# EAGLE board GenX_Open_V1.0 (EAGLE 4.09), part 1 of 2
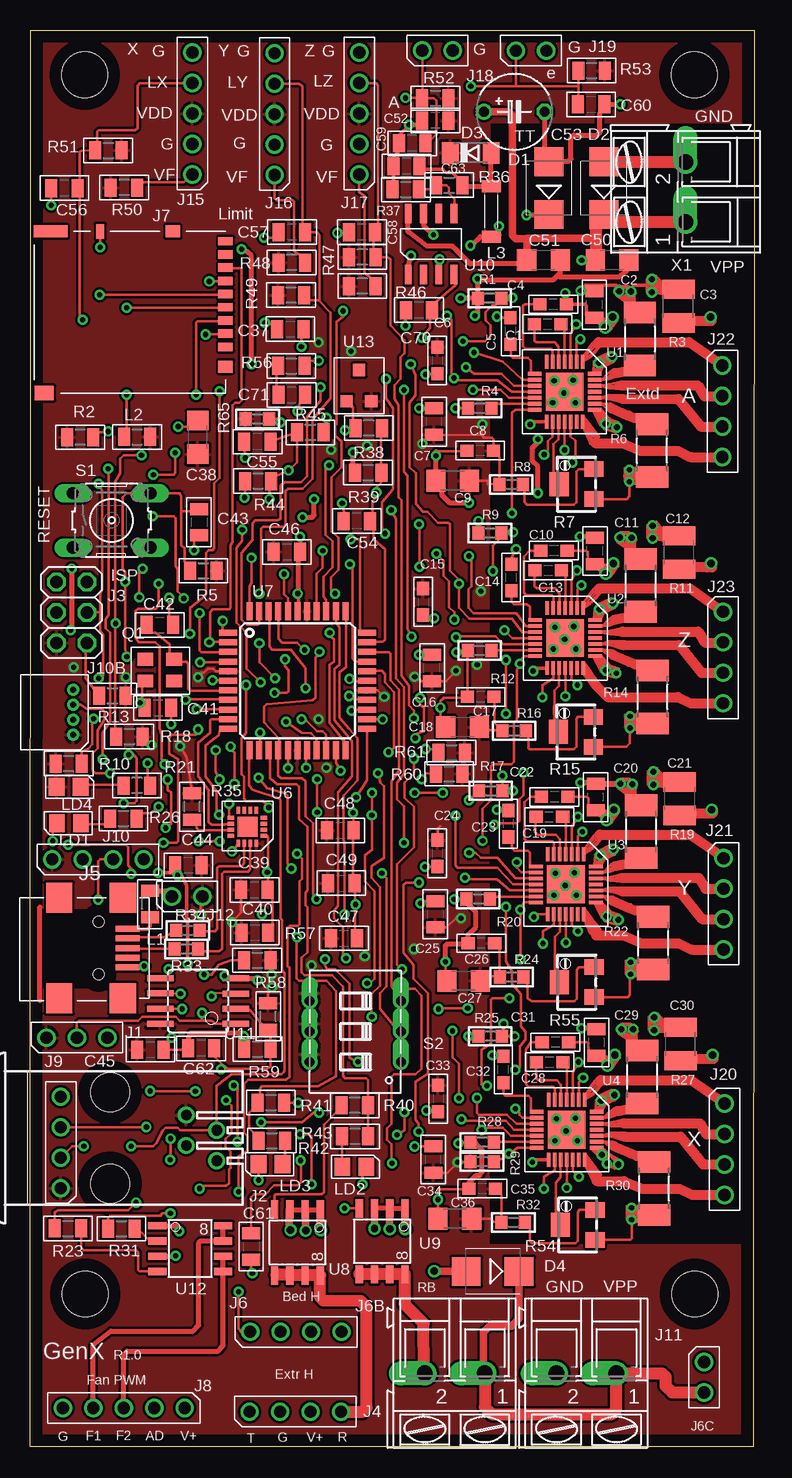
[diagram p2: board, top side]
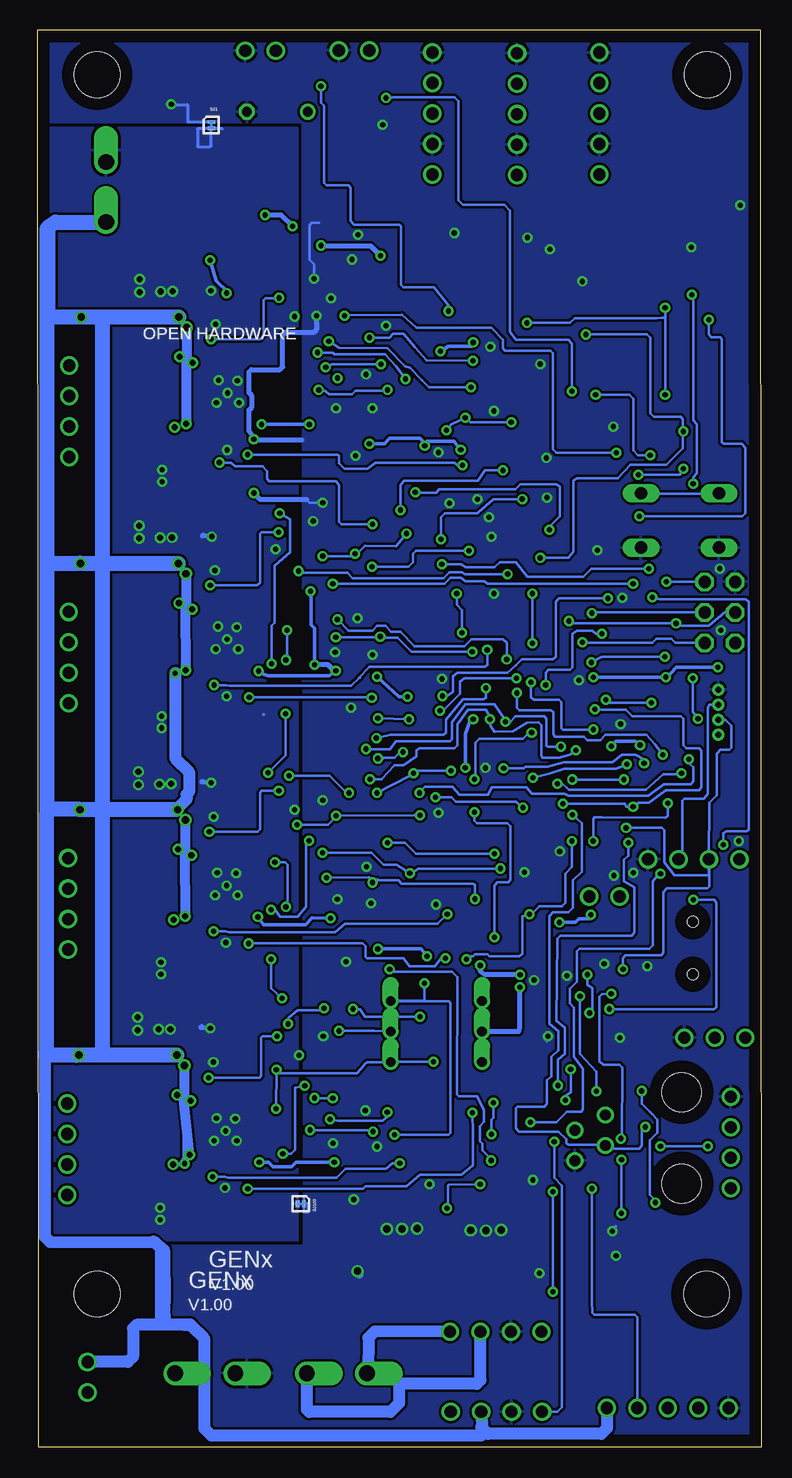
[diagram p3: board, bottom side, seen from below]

Size 60.4 x 118.06 mm. Coordinates in mm from the lower left corner, seen from the top.
Outline: 60.33,0 0,0 0.08,118.06 60.4,118.06 60.33,0
Copper layers used: Top, Bottom
Holes 3.81 mm at 4.6,12.73 55.42,12.73 4.55,114.33 55.4,114.33

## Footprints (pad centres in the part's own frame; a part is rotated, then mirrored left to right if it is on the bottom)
C0603 = smd 1.1 x 1: 1 -1.104,0; 2 1.104,0
C0805 = smd 1 x 1.5: 1 -1.1,0; 2 1.1,0
C1210 = smd 1.6 x 2.7: 1 -1.4,0; 2 1.4,0
C1206 = smd 1.6 x 1.8: 1 -1.4,0; 2 1.4,0
TAP5-60 = drill 0.813 round: + -2.54,0 | drill 0.813 octagon: - 2.54,0
SMB = smd 2.4 x 2.4: A 2.2,0; C -2.2,0
SOD80C = smd 1.4 x 1.8: A 1.7,0; C -1.7,0
520241-2 = drill 0.889 round: 1 -1.905,6.35; 2 -0.635,8.89; 3 0.635,6.35; 4 1.905,8.89 | hole 3.251: -3.81,0; 3.81,0
1X4ROUND = drill 1.016 round: 1 -3.81,0; 2 -1.27,0; 3 1.27,0; 4 3.81,0
2X03 = drill 1.016 octagon: 1 -2.54,-1.27; 2 -2.54,1.27; 3 0,-1.27; 4 0,1.27; 5 2.54,-1.27; 6 2.54,1.27
USB-BMINI = smd 0.5 x 2: 1 -1.6,2.4; 2 -0.8,2.4; 3 0,2.4; 4 0.8,2.4; 5 1.6,2.4 | smd 2.5 x 2.2: P$6 -4.2,2; P$7 4.2,2; P$8 4.2,-3.3; P$9 -4.2,-3.3 | hole 0.9: -2.182,0; 2.182,0
AK300/2 = drill 1.321 offset: 1 -2.515,0; 2 2.489,0
1X2ROUND = drill 1.016 round: 1 -1.27,0; 2 1.27,0
USD2 = smd 0.7 x 1.2: 1 3.85,0; 2 2.75,0; 3 1.65,0; 4 0.55,0; 5 -0.55,0; 6 -1.65,0; 7 -2.75,0; 8 -3.85,0; 9 -4.95,0 | smd 1.2 x 0.7: 10 -5.775,-10.45 | smd 1 x 2.8: P$1 -5.775,-14.575 | smd 1 x 1.2: P$9 5.5,0; P$10 -5.775,-4.4 | smd 1.2 x 1.6: P$11 7.7,-15.125
1X5ROUND = drill 1.016 round: 1 -5.08,0; 2 -2.54,0; 3 0,0; 4 2.54,0; 5 5.08,0
1X3ROUND = drill 1.016 round: 1 -2.54,0; 2 0,0; 3 2.54,0
1X4MOLEX = drill 0.5 pad 0.9 round: 1 1.875,0; 2 0.625,0; 3 -0.625,0; 4 -1.875,0
R0805 = smd 1 x 1.5: 1 -1.1,0; 2 1.1,0
L4516C = smd 1 x 1.6: 1 -2.1,0; 2 2.1,0
805SMT = smd 1.3 x 1.5: P$1 -1,0; P$2 1,0
ABM8 = smd 1.3 x 1.05: 1 -1.2,-0.9; 2 1.2,-0.9; 3 1.2,0.9; 4 -1.2,0.9
R0603 = smd 1 x 1.1: 1 -0.977,0; 2 0.977,0
R2010 = smd 1.8 x 2.7: 1 -2.2,0; 2 2.2,0
RTRIM5W = smd 1.3 x 1.6: 1 -1.25,-1.45; 3 1.25,-1.45 | smd 2 x 1.6: 2 0,1.45
B3F-10XX = drill 1.016 long: 1 -3.251,2.261; 2 3.251,2.261; 3 -3.251,-2.261; 4 3.251,-2.261
DIP03YL = drill 0.813 offset: 1 -2.54,-3.81; 2 0,-3.81; 3 2.54,-3.81; 4 2.54,3.81; 5 0,3.81; 6 -2.54,3.81
SJS = smd 0.305 x 0.61: 1 -0.267,0; 2 0.267,0
QFN28ET = smd 1.15 x 0.3: 1 -2.5,1.5; 2 -2.5,1; 3 -2.5,0.5; 4 -2.5,0; 5 -2.5,-0.5; 6 -2.5,-1; 7 -2.5,-1.5; 15 2.5,-1.5; 16 2.5,-1; 17 2.5,-0.5; 18 2.5,0; 19 2.5,0.5; 20 2.5,1; 21 2.5,1.5 | smd 0.3 x 1.15: 8 -1.5,-2.5; 9 -1,-2.5; 10 -0.5,-2.5; 11 0,-2.5; 12 0.5,-2.5; 13 1,-2.5; 14 1.5,-2.5; 22 1.5,2.5; 23 1,2.5; 24 0.5,2.5; 25 0,2.5; 26 -0.5,2.5; 27 -1,2.5; 28 -1.5,2.5 | smd 3.15 x 3.15: P$1 0,0
QFN16-3 = smd 0.55 x 0.3: 1 -1.375,0.75; 2 -1.375,0.25; 3 -1.375,-0.25; 4 -1.375,-0.75; 9 1.375,-0.75; 10 1.375,-0.25; 11 1.375,0.25; 12 1.375,0.75 | smd 0.3 x 0.55: 5 -0.75,-1.375; 6 -0.25,-1.375; 7 0.25,-1.375; 8 0.75,-1.375; 13 0.75,1.375; 14 0.25,1.375; 15 -0.25,1.375; 16 -0.75,1.375 | smd 1.65 x 1.65: P$1 0,0
TQFP44 = smd 1.5 x 0.5: 1 -5.8,4; 2 -5.8,3.2; 3 -5.8,2.4; 4 -5.8,1.6; 5 -5.8,0.8; 6 -5.8,0; 7 -5.8,-0.8; 8 -5.8,-1.6; 9 -5.8,-2.4; 10 -5.8,-3.2; 11 -5.8,-4; 23 5.8,-4; 24 5.8,-3.2; 25 5.8,-2.4; 26 5.8,-1.6; 27 5.8,-0.8; 28 5.8,0; 29 5.8,0.8; 30 5.8,1.6; 31 5.8,2.4; 32 5.8,3.2; 33 5.8,4 | smd 0.5 x 1.5: 12 -4,-5.8; 13 -3.2,-5.8; 14 -2.4,-5.8; 15 -1.6,-5.8; 16 -0.8,-5.8; 17 0,-5.8; 18 0.8,-5.8; 19 1.6,-5.8; 20 2.4,-5.8; 21 3.2,-5.8; 22 4,-5.8; 34 4,5.8; 35 3.2,5.8; 36 2.4,5.8; 37 1.6,5.8; 38 0.8,5.8; 39 0,5.8; 40 -0.8,5.8; 41 -1.6,5.8; 42 -2.4,5.8; 43 -3.2,5.8; 44 -4,5.8
SO-8 = smd 0.61 x 1.524: 1 -1.905,-2.743; 2 -0.635,-2.743; 3 0.635,-2.743; 4 1.905,-2.743; 5 1.905,2.743; 6 0.635,2.743; 7 -0.635,2.743; 8 -1.905,2.743
SO8 = smd 0.559 x 1.651: 1 -1.905,-2.54; 2 -0.635,-2.54; 3 0.635,-2.54; 4 1.905,-2.54; 5 1.905,2.54; 6 0.635,2.54; 7 -0.635,2.54; 8 -1.905,2.54
SOIC-8 = smd 0.5 x 2.2: 1 -1.905,-3.154; 2 -0.645,-3.154; 3 0.625,-3.154; 4 1.895,-3.154; 5 1.905,3.154; 6 0.635,3.154; 7 -0.635,3.154; 8 -1.905,3.154
SOT-23 = smd 1.03 x 1.03: 1 -1.038,-1.038; 2 1.038,-1.038; 3 0,1.556

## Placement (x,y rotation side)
C1  0.1uF  [C0603]  43.64,95.2 180 top
C2  0.1uF  [C0805]  47.07,95.17 90 top
C3  10uF  [C1210]  54.08,95.05 90 top
C4  0.1uF  [C0603]  43.15,93.55 0 top
C5  0.22uF  [C0603]  40.08,92.96 90 top
C6  0.1uF  [C0603]  33.96,90.53 270 top
C7  0.1uF  [C0805]  33.71,85.42 90 top
C8  0.1uF  [C0603]  37.54,83.01 180 top
C9  10uF  [C1206]  35.26,80.49 180 top
C10  0.1uF  [C0603]  43.69,74.68 180 top
C11  0.1uF  [C0805]  47.12,74.65 90 top
C12  10uF  [C1210]  54.13,74.52 90 top
C13  0.1uF  [C0603]  43.21,73.03 0 top
C14  0.22uF  [C0603]  40.13,72.44 90 top
C15  0.1uF  [C0603]  32.79,70.41 270 top
C16  0.1uF  [C0805]  33.53,64.9 90 top
C17  0.1uF  [C0603]  37.59,62.48 180 top
C18  10uF  [C1206]  36.07,59.97 180 top
C19  0.1uF  [C0603]  43.74,54.15 180 top
C20  0.1uF  [C0805]  47.17,54.13 90 top
C21  10uF  [C1210]  54.18,54 90 top
C22  0.1uF  [C0603]  43.31,52.5 0 top
C23  0.22uF  [C0603]  39.9,51.92 90 top
C24  0.1uF  [C0603]  33.96,49.45 270 top
C25  0.1uF  [C0805]  33.81,44.37 90 top
C26  0.1uF  [C0603]  37.64,41.96 180 top
C27  10uF  [C1206]  36.17,38.81 180 top
C28  0.1uF  [C0603]  43.81,33.71 180 top
C29  0.1uF  [C0805]  47.24,33.68 90 top
C30  10uF  [C1210]  54.25,33.55 90 top
C31  0.1uF  [C0603]  43.33,32.05 0 top
C32  0.22uF  [C0603]  39.47,31.45 90 top
C33  0.1uF  [C0603]  34.04,29.01 270 top
C34  0.1uF  [C0805]  33.63,23.93 90 top
C35  0.1uF  [C0603]  37.72,21.51 180 top
C36  10uF  [C1206]  35.43,19 180 top
C37  10uF  [C0805]  21.72,93.14 0 top
C38  100uF  [C1206]  14,84.12 90 top
C39  0.1uF  [C0805]  18.72,46.41 0 top
C40  2.2uF  [C0805]  18.75,42.85 0 top
C41  33pF  [C0805]  10.67,61.57 0 top
C42  33pF  [C0805]  10.82,68.48 0 top
C43  0.1uF  [C0805]  14.1,77.04 270 top
C44  0.1uF  [C0805]  13.21,48.44 180 top
C45  2.2uF  [C0805]  10.03,33.1 0 top
C46  0.1uF  [C0805]  21.41,74.57 0 top
C47  0.1uF  [C0805]  26.19,42.37 0 top
C48  0.1uF  [C0805]  25.88,51.36 0 top
C49  0.1uF  [C0805]  25.96,46.96 0 top
C50  4.7uF  [C1206]  48.54,98.91 0 top
C51  4.7uF  [C1206]  42.82,98.91 0 top
C52  10uF  [C0805]  33.81,110.52 180 top
C53  100uF  [TAP5-60]  40.39,111.25 0 top
C54  10uF  [C0805]  27.25,77.14 180 top
C55  10uF  [C0805]  18.97,83.74 180 top
C56  10uF  [C0805]  2.87,104.88 180 top
C57  10uF  [C0805]  21.84,101.22 180 top
C58  10uF  [C0805]  27.69,101.22 180 top
C59  10uF  [C0805]  31.88,108.61 180 top
C60  10uF  [C0805]  46.79,111.86 0 top
C61  0.1uF  [C0805]  18.44,16.69 270 top
C62  10uF  [C0805]  14.27,33.2 180 top
C63  10uF  [C0805]  31.39,106.71 180 top
C70  220pF  [C0805]  32.44,94.72 180 top
C71  22nF  [C0805]  21.82,87.66 0 top
D1  STPS2L40U  [SMB]  43.28,104.88 90 top
D2  [SMB]  47.85,104.88 90 top
D3  [SOD80C]  36.75,107.82 0 top
D4  [SMB]  38.58,14.61 180 top
J1  [520241-2]  6.68,25.73 270 top
J2  PINH-1X4RR40  [1X4ROUND]  2.57,25.35 90 top
J3  [2X03]  3.48,69.52 90 top
J4  PINH-1X4RR40  [1X4ROUND]  22.12,2.92 0 top
J5  USB-BMINI  [USB-BMINI]  5.74,41.55 270 top
J6  PINH-1X4RR40  [1X4ROUND]  22.17,9.58 0 top
J6B  [AK300/2]  35.41,6.12 180 top
J6C  PINH-1X2RR40  [1X2ROUND]  56.21,5.79 270 top
J7  MICROSD  [USD2]  16.31,95.5 270 top
J8  PINH-1X5RR40  [1X5ROUND]  7.82,3.23 180 top
J9  PINH-1X3RR40  [1X3ROUND]  3.91,34.09 0 top
J10  PINH-1X4RR40  [1X4ROUND]  5.66,48.95 0 top
J10B  PINH-1X4MOLEX  [1X4MOLEX]  3.61,61.19 270 top
J11  [AK300/2]  46.38,6.12 180 top
J12  PINH-1X2RR40  [1X2ROUND]  13.11,45.85 0 top
J15  PINH-1X5RR40  [1X5ROUND]  13.54,111.1 90 top
J16  PINH-1X5RR40  [1X5ROUND]  20.4,111.05 90 top
J17  PINH-1X5RR40  [1X5ROUND]  27.46,111.1 90 top
J18  PINH-1X2RR40  [1X2ROUND]  33.99,116.36 0 top
J19  PINH-1X2RR40  [1X2ROUND]  41.78,116.33 0 top
J20  PINH-1X4RR40  [1X4ROUND]  57.91,24.79 270 top
J21  PINH-1X4RR40  [1X4ROUND]  57.84,45.24 270 top
J22  PINH-1X4RR40  [1X4ROUND]  57.73,86.28 270 top
J23  PINH-1X4RR40  [1X4ROUND]  57.78,65.76 270 top
L1  [R0805]  10.01,45.21 90 top
L2  [R0805]  8.94,84.15 0 top
L3  10uH  [L4516C]  38.48,102.95 90 top
LD1  GRN  [805SMT]  3.25,51.97 180 top
LD2  LED805SMT  [805SMT]  27.05,23.34 0 top
LD3  LED805SMT  [805SMT]  20.07,23.52 180 top
LD4  GRN  [805SMT]  3.23,54.99 0 top
Q1  20MHz  [ABM8]  10.82,64.72 0 top
R1  100K  [R0603]  38.33,95.71 0 top
R2  10K  [R0805]  4.19,84.12 180 top
R3  0.15R  [R2010]  50.85,92.3 270 top
R4  10K  [R0603]  37.52,86.54 180 top
R5  10K  [R0805]  14.45,73 0 top
R6  0.15R  [R2010]  51.87,83.01 90 top
R7  10K  [RTRIM5W]  45.57,80.21 90 top
R8  10K  [R0603]  40.13,80.19 0 top
R9  100K  [R0603]  38.35,76.15 0 top
R10  10K  [R0805]  3.23,56.92 180 top
R11  0.15R  [R2010]  50.9,71.78 270 top
R12  10K  [R0603]  37.49,66.34 180 top
R13  10K  [R0805]  6.88,62.59 0 top
R14  0.15R  [R2010]  51.92,62.48 90 top
R15  10K  [RTRIM5W]  45.52,59.56 90 top
R16  10K  [R0603]  40.39,59.66 0 top
R17  100K  [R0603]  38.43,54.66 0 top
R18  10K  [R0805]  8.28,59.18 0 top
R19  0.15R  [R2010]  50.95,51.26 270 top
R20  10K  [R0603]  37.36,45.64 180 top
R21  1K  [R0805]  8.92,55.09 180 top
R22  0.15R  [R2010]  51.97,41.96 90 top
R23  270R  [R0805]  3.17,18.19 0 top
R24  10K  [R0603]  40.16,39.14 0 top
R25  100K  [R0603]  38.38,34.21 0 top
R26  1K  [R0805]  7.8,52.35 0 top
R27  0.15R  [R2010]  51.03,30.81 270 top
R28  10K  [R0603]  37.69,25.37 180 top
R29  100K  [R0603]  37.69,23.75 180 top
R30  0.15R  [R2010]  52.04,21.51 90 top
R31  270R  [R0805]  7.62,18.16 0 top
R32  10K  [R0603]  40.31,18.69 0 top
R33  33R  [R0603]  13.03,41.48 0 top
R34  33R  [R0603]  13.16,43.03 0 top
R35  10K  [R0805]  13.51,53.34 90 top
R36  11K  [R0805]  34.95,105.13 0 top
R37  3.6K  [R0805]  31.34,104.78 0 top
R38  4.7K  [R0805]  28.24,84.89 180 top
R39  470R  [R0805]  28.19,81.18 0 top
R40  270R  [R0805]  27.08,28.45 180 top
R41  270R  [R0805]  20.09,28.68 0 top
R42  1K  [R0805]  20.17,25.5 0 top
R43  1K  [R0805]  27.1,25.86 180 top
R44  470R  [R0805]  19.02,80.47 0 top
R45  4.7K  [R0805]  23.37,84.53 0 top
R46  180R  [R0805]  27.71,96.72 180 top
R47  1K  [R0805]  27.71,99.14 180 top
R48  180R  [R0805]  21.82,98.68 180 top
R49  1K  [R0805]  21.77,95.96 180 top
R50  180R  [R0805]  7.85,104.93 180 top
R51  1K  [R0805]  6.53,108.03 0 top
R52  10K  [R0805]  33.81,112.37 0 top
R53  10K  [R0805]  46.84,114.68 0 top
R54  10K  [RTRIM5W]  45.67,18.49 90 top
R55  10K  [RTRIM5W]  45.59,38.71 90 top
R56  4.7K  [R0805]  21.79,90.07 0 top
R57  10K  [R0805]  18.95,40.54 0 top
R58  10K  [R0805]  19.86,35.86 90 top
R59  470R  [R0805]  18.97,33.15 0 top
R60  10K  [R0805]  34.95,56.08 0 top
R61  10K  [R0805]  35.15,57.84 0 top
R65  0R  [R0603]  18.97,85.65 0 top
S1  [B3F-10XX]  6.81,77.19 0 top
S2  [DIP03YL]  27.13,34.59 90 top
SJ1  [SJS]  45.9,110.13 270 bottom
SJ100  [SJS]  38.43,20.24 180 bottom
U1  A4988  [QFN28ET]  44.58,87.91 270 top
U2  A4988  [QFN28ET]  44.63,67.39 270 top
U3  A4988  [QFN28ET]  44.68,46.86 270 top
U4  A4988  [QFN28ET]  44.75,26.42 270 top
U6  XR21V1410  [QFN16-3]  18.14,51.66 180 top
U7  ATmega1284P  [TQFP44]  22.3,63.83 0 top
U8  NDS9410A  [SO-8]  22.3,17.02 180 top
U9  NDS9410A  [SO-8]  29.36,17.12 180 top
U10  L5970AD  [SO8]  33.45,100.23 0 top
U11  ATTINY45  [SOIC-8]  14.02,37.13 90 top
U12  NDS9956A  [SO-8]  13.36,16.51 270 top
U13  LM4041  [SOT-23]  27.43,88.16 0 top
X1  [AK300/2]  54.66,104.57 90 top

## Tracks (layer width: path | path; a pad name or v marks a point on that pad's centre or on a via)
ADN  (via drill 0.43)
  Top 0.203: C62.1 15.4,32.5 16.1,31.8 | 16.1,31.8 16.48,31.5 19.79,31.5 20.07,31.71 R59.2 20.07,34.54 19.84,34.77 | 19.84,34.77 | 19.84,34.77 R58.1 19.67,34.79 18.41,36.32 18.21,36.45 18.17,36.49 U11.2 | v16.36,28.88 16.82,28.42 16.82,26.14 16.33,25.65 16.33,24.94 16.71,24.56 16.71,23.24 16.59,23.11 16.59,21.97 16.36,21.74 14.38,21.74 v14.15,21.51 | v15.93,31.45 15.95,31.65 16.1,31.8
  Bottom 0.203: J8.2 10.36,10.77 10.59,11 13.95,11 14.12,11.18 14.15,12.12 v14.15,21.51 | v16.36,28.88 16.36,29.23 15.93,29.54 v15.93,31.45
D+
  Top 0.203: U6.15 18.36,50.06 18.36,48.11 18.19,47.93 16.2,47.93 16.03,47.75 16.03,41.48 15.77,41.3 14.12,41.3 R33.2
D-
  Top 0.203: U6.14 17.86,50.06 17.86,48.62 17.63,48.39 15.77,48.39 15.62,48.23 15.62,43.16 15.42,42.95 14.66,42.95 R34.2
DIR_A  (via drill 0.43)
  Top 0.203: U1.19 45.08,84.21 45.47,83.82 45.47,82.27 v45.21,82.02 | U7.37 23.9,72.75 24.41,73.25 24.41,73.48 v24.41,74.65 | v32.49,73.33 32.49,76.71 v32.44,76.86
  Bottom 0.203: v45.21,82.02 44.25,82.02 43.92,81.69 41.63,81.69 41.25,81.31 41.25,80.64 41.07,80.47 35.48,80.47 35.23,80.11 35.23,77.09 35.03,76.86 v32.44,76.86 | v24.41,74.65 28.8,74.65 29.06,74.42 29.06,73.71 29.44,73.33 v32.49,73.33
DIR_X  (via drill 0.43)
  Top 0.203: U4.19 45.26,22.97 v45.77,22.5 | v30.18,23.62 30.12,23.65 30.15,23.67 30.15,25.2 29.77,25.58 29.77,26.52 30.15,26.9 30.15,30.84 30.35,31.04 32.13,31.04 32.66,31.5 32.66,37.57 32.11,38.18 30.33,38.18 30.15,38.35 30.15,55.45 30.76,56.31 30.76,63.07 30.07,63.86 30.07,66.06 29.92,66.22 28.83,66.22 U7.31
  Bottom 0.203: v45.77,22.5 44.78,22.5 44.5,22.43 35.43,22.43 34.7,23.16 31.32,23.16 30.79,23.62 v30.18,23.62
DIR_Y  (via drill 0.43)
  Top 0.203: U3.19 45.18,43.42 v45.7,42.95 | v26.21,44.37 26.21,50.39 26.14,50.55 26.14,54.23 27.3,55.52 27.3,59.05 26.62,59.82 25.83,60.76 25.83,64.54 26.34,64.95 26.34,68.91 U7.34
  Bottom 0.203: v45.7,42.95 44.7,42.95 44.42,42.88 35.56,42.88 34.72,43.56 27.05,43.56 v26.21,44.37
DIR_Z  (via drill 0.43)
  Top 0.203: U2.19 45.13,63.94 v45.64,63.48 | v22.89,66.4 22.28,66.98 21.01,66.98 20.73,67.33 20.73,69.16 U7.41
  Bottom 0.203: 33.53,64.08 34.24,63.4 44.37,63.4 44.65,63.48 v45.64,63.48 | 33.53,64.08 33.5,64.08 | v22.89,66.4 22.89,65.18 23.06,65 32.69,65 33.55,64.08 33.53,64.08
EN_A  (via drill 0.43)
  Top 0.203: U1.2 45.58,91.98 v45.9,92.3 | 39.37,95.73 39.34,95.71 R1.2 | 39.37,95.73 v40.23,95.73 | v24.23,88.29 24.23,87.15 23.09,85.83 23.09,80.87 22.61,80.39 21.21,80.39 20.88,80.06 20.88,77.34 20.65,77.22 18.77,77.22 18.54,76.96 18.54,75.56 17.65,74.5 17.65,68.91 18.09,68.48 19,68.48 19.1,68.58 19.1,69.47 19.07,69.49 19.1,69.52 U7.43 | v36.09,92.13 37.95,92.13 38.38,92.56 38.38,93.47 38,93.85 38,94.54 38.58,95.12 38.81,95.12 39.37,95.68 39.37,95.73
  Bottom 0.203: v45.9,92.3 41.83,92.3 41.53,92.61 41.53,95.53 41.35,95.71 40.26,95.71 v40.23,95.73 | v24.23,88.29 27.74,88.29 28.32,88.88 29.34,89.92 29.74,90.02 31.22,91.54 35.23,91.57 v36.09,92.13
EN_X  (via drill 0.43)
  Top 0.203: U4.2 45.76,30.39 v46.13,30.76 | 39.42,34.21 R25.2 | 39.42,34.21 v40.41,34.21 | 39.42,34.21 39.4,34.24 39.32,34.24 39.5,34.42 v39.5,35.23 | U7.21 25.5,57 v25.91,56.34 | v29.03,56.11 29.23,55.35 29.52,55.04 29.52,49.1 28.47,48.39 28.47,47.4 29.18,46.61 29.18,38.43 28.5,37.74 v28.5,35.84 | v36.5,36.52 33.81,36.52 v34.06,36.47 | U3.2 45.68,50.89 v46.05,51.26 | v40.26,54.66 39.57,54.66 39.55,54.63 39.52,54.66 R17.2 39.41,55.89 v39.4,55.91 | v32.08,54.48 v34.42,54.48
  Bottom 0.203: v46.13,30.76 41.88,30.76 41.73,30.91 41.73,34.09 41.6,34.21 v40.41,34.21 | v25.91,56.34 28.96,56.34 v29.03,56.11 29.18,56.06 | v39.5,35.23 39.45,35.28 39.45,35.74 38.71,36.37 36.6,36.37 v36.5,36.52 | v34.06,36.47 33.48,36.45 33.07,35.84 v28.5,35.84 | v46.05,51.26 42.04,51.26 41.83,51.46 41.83,54.51 41.68,54.66 v40.26,54.66 | v34.42,54.48 34.62,54.48 36.04,55.91 v39.4,55.91 | 29.18,56.06 29.16,56.08 | 29.18,56.06 29.34,55.91 v32.08,54.48
EN_Z  (via drill 0.43)
  Top 0.203: U2.2 45.63,71.43 v45.97,71.78 | v40.28,76.2 R9.2 39.34,75.87 39.34,75.89 39.32,75.92 39.29,75.89 39.29,75.77 38.61,75.08 v38.61,72.97 | U7.40 21.5,70.7 21.18,71.02 v21.18,72.72
  Bottom 0.203: v45.97,71.78 42.06,71.78 41.83,72.01 41.83,76.07 41.71,76.2 v40.28,76.2 | v21.18,72.72 24.74,72.72 24.99,72.87 26.04,72.87 26.52,72.39 34.11,72.39 34.54,72.82 38.46,72.82 v38.61,72.97
ESTOP  (via drill 0.43)
  Top 0.203: v24.99,67.82 24.99,67.56 25.35,67.28 25.35,65.43 24.99,65.15 24.99,60.35 26.26,58.73 26.26,58.32 U7.22 | v25.43,71.09 25.12,71.4 25.12,72.47 25.73,73.08 25.73,75.74 25.15,76.28 25.15,80.8 25.98,81.64 25.98,83.77 25.45,84.25 25.45,85.11 25.55,85.19 25.55,93.73 26.11,94.18 v26.11,94.64 | 45.74,113.36 45.74,112.37 C60.1 | 40.51,113.36 45.74,113.36 | 40.51,113.36 J19.1 | 40.51,113.36 40.49,113.36 40.46,113.39 40.44,113.36 v36.75,113.36 | 45.74,113.36 45.74,113.87 45.74,114.09 R53.1
  Bottom 0.203: v24.99,67.82 24.99,69.72 25.43,70.16 v25.43,71.09 | v26.11,94.64 26.11,95.12 27.3,96.62 29.84,96.62 30.07,96.85 30.07,101.7 30.2,101.83 33.98,101.83 34.29,102.16 34.29,104.9 34.47,105.13 36.3,105.13 36.5,105.33 36.5,111.73 36.75,111.99 v36.75,113.36
GND  (via drill 0.43, 0.61)
  Top 0.203: R17.1 v36.6,53.87 | C25.2 32.72,45.47 v32.56,45.29 | R20.2 36.07,45.62 v35.38,45.62 | C24.2 32.92,48.35 v32.94,48.34 | C27.2 34.77,39.27 34.65,39.4 v34.65,40.41 | 34.77,41.91 34.85,41.91 34.8,41.91 | 36.37,41.91 36.42,41.96 C26.2 | R25.1 v36.55,34.21 | C34.2 33.18,25.03 v32.08,25.02 | R28.2 36.02,25.38 v35.74,25.3 | C33.2 32.99,27.9 v33.05,28.02 | C36.2 34.03,21.46 34.19,21.46 | C35.2 36.5,21.51 36.45,21.46 34.19,21.46 | 34.19,21.46 34.04,21.44 v34.01,20.6 | C7.2 32.62,86.52 v32.46,86.54 | v35.48,86.54 R4.2 | C6.2 33.25,89.4 v32.99,89.36 | 33.85,82.95 34.01,82.96 | C8.2 36.32,83.01 36.27,82.96 34.01,82.96 | 34.01,82.96 33.88,82.93 v33.86,82.58 | R9.1 v37.39,77.14 | C16.2 32.67,66 v32.44,65.99 | v35.56,66.22 35.89,66.34 R12.2 36.59,66.15 36.6,66.14 36.49,66.03 C17.2 36.37,62.48 36.32,62.43 35.05,62.43 | C15.2 32.84,69.03 v33.71,69.04 | C18.2 34.24,60.45 34.24,61.57 34.24,62.15 | 34.24,62.15 34.49,62.43 34.9,62.43 35.05,62.43 | 35.05,62.43 34.54,62.43 34.24,62.15 | 34.24,62.15 v34.24,61.59 | 47.52,111.18 C60.2 | 27.1,45.19 27.1,43.1 C47.2 | 27.1,45.19 27.1,46.25 C49.2 26.95,47.68 26.95,50.98 C48.2 26.98,52.15 v26.95,52.83 | 19.84,47.88 19.84,47.12 C39.2 20.24,45.62 20.24,43.59 C40.2 | 19.84,47.88 19.84,50.77 19.79,50.9 U6.1 | 49.73,97.97 C50.2 | v22.33,86.31 22.48,86.89 C71.2 | U7.39 22.38,70.33 | 22.38,73.84 C46.2 22.61,75.39 v22.53,75.82 | v16.84,49.61 17.37,50.19 U6.13 | v5.87,99.95 5.87,100.71 J7.10 | v14.96,97.1 15.72,97.1 J7.6 | v15.24,63.88 15.77,63.88 U7.6 | v23.04,56.57 23.04,57.33 U7.18 | v26.64,63.98 26.64,63.78 27.36,63.78 U7.28 | v34.16,98.93 34.16,98.48 U10.3 | v18.54,14.45 18.44,14.73 C61.2 | J5.5 9.12,39.9
  Top 0.203: v11.81,34.09 11.2,33.15 C45.2 13.01,33.1 13.13,32.59 C62.2 | v12.32,47.6 12.32,47.73 C44.2 | v11.76,60.22 11.76,60.83 C41.2 | v11.61,70.74 11.61,69.14 C42.2 | v13.69,74.7 13.69,75.46 C43.2 | v26.04,78.61 26.19,77.85 C54.2 | v22.63,91.67 22.63,92.43 C37.2 | v19.53,100.76 20.3,100.76 C57.2 | v25.63,101.14 26.26,101.14 C58.2 | v31.32,93.42 31.32,94 C70.2 | v27.71,21.87 27.71,22.63 LD2.P$2 | v1.91,50.47 1.91,51.23 LD1.P$2 | v12.37,85.01 13.13,85.01 C38.2 | 22.38,71.09 v22.33,71.09 | 44.22,97.81 C51.2 | R1.1 37.34,96.24 | 32.64,110.21 C52.2 | 19.84,47.88 v19.79,47.88 | 27.1,45.19 v27.15,45.19 | 42.93,108.03 D1.A | C44.2 11.68,47.83 | 12.42,48.06 11.99,48.46 C44.2 | 18.11,99.59 v17.65,99.8 | v37.31,97.33 37.57,97.41 37.36,97.41 37.36,96.29 37.34,95.94 | 42.34,83.69 v42.34,83.95 | 34.37,79.63 C9.2 | 18.79,39.03 v18.97,38.89 | 17.87,33.37 R59.1 | 12.27,18.41 v12.45,17.96 | 12.12,15.88 v12.14,15.9 | R44.1 17.93,79.08 v17.91,79.1 | C55.2 17.93,82.43 v17.96,82.4 | 31.6,110.08 v31.6,110.16 | C59.2 30.83,109.31 | C56.2 1.77,103.46 v1.78,103.45 | LD3.P$2 19.07,22.23 v19.07,22.23
  Top 0.254: C60.2 47.83,111.86 | 30.78,107.94 C59.2 | C63.2 30.29,106.9 30.35,106.96 | R37.1 30.24,104.84 30.29,104.89
  Top 0.305: 22.38,70.33 22.38,71.09 | 9.12,39.9 v9.53,40.06 | 11.68,47.83 v10.69,47.83 | 12.42,48.06 13.08,46.76 13.08,43.94 13.13,43.87 v13.13,40.26 | 30.83,109.31 31.6,110.08 | 30.78,107.94 30.35,107.52 30.35,106.96 | 30.29,104.89 C63.2
  Top 0.406: 34.85,41.91 36.37,41.91 | v34.65,40.41 34.65,41.76 34.8,41.91 | R1.1 v35.92,95.71 | C9.2 33.85,82.95 | 47.52,111.18 47.52,109.55 47.27,109.3 45.34,109.3 45.11,109.07 45.11,107.31 44.91,107.11 44.48,107.11 D1.A | 49.73,97.97 49.12,97.48 44.2,97.48 C51.2 | 22.38,71.09 22.38,73.84 | U8.1 U8.2 U8.3 22.94,19.71 | U9.1 U9.2 U9.3 | 44.22,97.81 43.66,97.26 37.34,97.26 37.34,96.24 | v31.6,110.16 32.64,110.21 | 42.93,108.03 C53.- | 18.11,99.59 18.47,99.24 v18.47,90.22 | v22.73,77.44 23.52,77.44 23.7,77.62 v23.7,78.94 | 37.34,95.94 37.34,94.51 v37.11,94.23 | v42.34,79.48 42.34,81.69 41.91,82.12 41.91,83.26 42.34,83.69 | v36.6,78.66 34.98,78.66 34.37,79.27 34.37,79.63 | 18.79,39.03 U11.4 16.75,39.03 v16.23,39.24 | 17.87,33.37 v17.83,34.21 17.88,34.49 13.44,34.49 13.23,34.05 C62.2 | U12.1 12.27,18.41 | U12.3 12.12,15.88 | C26.2 36.54,42.66 37.19,43.31 37.19,44.58 36.39,45.38 R20.2 | C35.2 36.62,22.01 37.21,22.61 37.52,22.61 37.69,22.91 37.69,24.71 37.11,25.38 R28.2 | R39.1 26.96,81.45 v26.95,82.86 | U10.7 32.82,101.78 v33.66,100.99 | v3.4,68.05 3.53,68.02 3.53,73.08 3.5,73.15 v3.48,73.18 | C60.2 v49.23,111.86
  Top 0.61: U8.1 24.21,18.09 v24.26,18.03 | 21.61,18.06 21.61,19.76 U8.3 | 22.96,19.68 22.96,18.01 22.94,17.98 | 22.96,19.68 22.96,19.71 | 22.94,19.71 22.96,19.68 | U9.3 v28.73,18.19 | 29.97,18.16 30,18.19 U9.2 | 31.24,18.14 31.27,18.16 U9.1 | D4.A 33.73,14.61 v33.71,14.63
  Bottom 0.203: SJ100.1 38.16,20.89 38.18,19.56 37.85,19.56 37.85,20.27 38.21,20.28 38.23,20.3 | v34.24,61.59 34.19,61.62 34.24,61.62 | C53.- 42.88,111.18 | 36.91,102.01 37.52,101.98 37.72,101.8 37.72,98.93 37.31,98.53 v37.31,97.33 | 42.19,83.9 42.29,84 v42.34,83.95 | 38.33,83.9 38.25,83.87 | 37.95,78.92 37.69,78.66 v36.6,78.66 | v42.34,79.48 42.34,79.45 | v26.95,52.83 27.08,52.83 27,52.76 | v18.97,38.89 18.9,38.94 | v17.83,34.21 17.91,33.78 | v12.45,17.96 12.17,18.39 12.19,18.36 | v12.14,15.9 12.14,15.98 12.19,16.03 | v17.96,82.4 17.96,82.37 18.03,82.3 | v1.78,103.45 1.7,103.38 | v19.07,22.23 19.07,22.15 19.05,22.12
  Bottom 0.254: SJ1.1 47.85,110.4 47.85,111.81 47.9,111.81 47.9,111.84 49.23,111.84 v49.23,111.86
  Bottom 0.406: v37.11,94.23 37.08,93.14 37.34,92.89 39.7,92.89 39.93,92.66 39.93,89.99 40.16,89.76 42.55,89.76 42.75,89.56 42.75,87.83 42.49,87.58 42.49,86.64 42.75,86.39 42.75,84.66 42.29,84 | 42.19,83.9 38.33,83.9 | v42.34,79.48 41.78,78.92 37.95,78.92 | v16.23,39.24 16.23,39.27 16.31,39.34 | v26.95,82.86 26.92,82.86 26.92,82.88 | v33.66,100.99 33.88,100.99
  Bottom 0.61: v24.26,18.03 24.26,17.93 24.16,17.83 | v28.73,18.19 28.73,18.21 28.7,18.19 | v33.71,14.63 33.71,14.5 33.53,14.33
  other vias: 21.72,18.06 22.99,18.01 30,18.14 31.27,18.14
  pour Bottom: 0.18,117.96 60.3,117.96 60.3,114 60.33,110.36 38.28,110.39 38.28,110.24 38.18,17.12 38.2,16.76 60.22,16.79 60.2,0.15 0.1,0.1
GND1  (via drill 0.43, 0.51)
  Top 0.203: U3.3 45.18,51.71 v45.7,52.5 | C23.2 39.23,53.02 v38.94,53.09 | v44.68,42.01 U3.18 | 49.88,39.44 49.89,39.45 49.94,39.6 49.94,39.5 v50.09,39.37 50.09,39.24 50.04,39.19 50.04,37.64 49.85,37.46 R55.1 | 49.28,55.68 49.99,55.68 50.01,54.91 50.01,54.61 49.89,54.69 49.68,54.69 49.94,54.43 49.96,54.43 49.91,54.38 49.73,54.38 49.05,54.86 49.25,55.55 49.28,55.52 50.09,55.55 | 50.09,55.55 50.42,55.5 v50.22,55.22 | v50.22,55.22 50.22,55.09 49.68,54.59 49.78,54.97 49.63,54.81 49.58,54.66 49.35,54.86 | 51.54,56.26 51.54,55.22 52.7,55.22 52.78,55.3 52.78,56.03 52.27,56.54 52.22,56.36 | 52.22,56.36 52.6,55.98 52.6,55.35 52.38,55.35 52.45,55.42 52.45,56.01 52.27,56.01 52.27,55.58 52.15,55.58 52.12,55.6 52.12,55.73 51.61,55.73 51.61,55.85 51.64,55.88 51.64,55.6 | 52.22,56.36 52.09,56.36 v51.97,56.24 | 50.09,55.55 50.49,54.36 50.49,54.89 50.62,55.07 v50.22,55.22 | U4.3 45.26,31.26 v45.72,32.05 | C32.2 39.31,32.58 v38.58,32.61 | v44.76,21.57 U4.18 | 49.95,18.99 49.96,19 50.01,19.15 50.01,19.05 v50.16,18.92 50.19,18.9 50.19,17.37 50.06,17.24 R54.1 | 49.35,35.23 50.06,35.23 50.09,34.47 50.09,34.16 49.96,34.24 49.76,34.24 50.01,33.98 50.04,33.98 49.99,33.93 49.81,33.93 49.12,34.42 49.33,35.1 49.35,35.08 50.16,35.1 | 50.16,35.1 50.49,35.05 v50.29,34.77 | v50.29,34.77 50.29,34.65 49.76,34.14 49.86,34.52 49.71,34.37 49.66,34.21 49.43,34.42 | 51.61,35.81 51.61,34.77 52.78,34.77 52.86,34.85 52.86,35.59 52.35,36.09 52.3,35.92 | 52.3,35.92 52.68,35.53 52.68,34.9 52.45,34.9 52.53,34.98 52.53,35.56 52.35,35.56 52.35,35.13 52.22,35.13 52.2,35.15 52.2,35.28 51.69,35.28 51.69,35.41 51.71,35.43 51.71,35.15
  Top 0.203: 52.3,35.92 52.17,35.92 v52.05,35.79 | 50.16,35.1 50.57,33.91 50.57,34.44 50.7,34.62 v50.29,34.77 | U2.3 45.13,72.23 v45.59,73.03 | C14.2 40.17,74.18 v40.54,74.78 | v44.63,62.53 U2.18 | 49.84,59.97 49.89,60.12 49.89,60.02 v50.04,59.89 50.04,58.62 49.73,58.31 R15.1 | 49.23,76.2 49.94,76.2 49.96,75.44 49.96,75.13 49.84,75.21 49.63,75.21 49.89,74.95 49.91,74.95 49.86,74.91 49.68,74.91 49,75.39 49.2,76.07 49.23,76.05 50.04,76.07 | 50.04,76.07 50.37,76.02 v50.16,75.74 | v50.16,75.74 50.16,75.62 49.63,75.11 49.73,75.49 49.58,75.34 49.53,75.18 49.3,75.39 | 51.49,76.78 51.49,75.74 52.65,75.74 52.73,75.82 52.73,76.56 52.22,77.06 52.17,76.89 | 52.17,76.89 52.55,76.5 52.55,75.87 52.32,75.87 52.4,75.95 52.4,76.53 52.22,76.53 52.22,76.1 52.09,76.1 52.07,76.12 52.07,76.25 51.56,76.25 51.56,76.38 51.59,76.4 51.59,76.12 | 52.17,76.89 52.05,76.89 v51.92,76.76 | 50.04,76.07 50.44,74.88 50.44,75.41 50.57,75.59 v50.16,75.74 | U1.3 45.08,92.75 v45.54,93.55 | C5.2 39.13,94.07 v38.94,94.18 | v44.58,83.06 U1.18 | 49.78,80.49 49.84,80.64 49.84,80.54 v49.99,80.42 49.99,79.2 49.75,78.96 R7.1 | 49.99,96.6 49.17,96.57 49.15,96.6 48.95,95.91 49.63,95.43 49.81,95.43 49.86,95.48 49.84,95.48 49.58,95.73 49.78,95.73 49.91,95.66 49.91,95.96 49.89,96.72 49.17,96.72 49.15,96.8 v49.12,96.29 48.9,96.8 | 49.99,96.6 50.32,96.55 v50.11,96.27 | v50.11,96.27 50.11,96.14 49.58,95.63 49.68,96.01 49.53,95.86 49.48,95.71 49.25,95.91 | 51.44,97.31 51.44,96.8 51.44,96.27 52.6,96.27 52.68,96.34 52.68,97.08 | 52.68,97.08 52.17,97.59 52.12,97.41 | 52.12,97.41 52.5,97.03 52.5,96.39 52.27,96.39 52.35,96.47 52.35,97.05 52.17,97.05 52.17,96.62 52.05,96.62 52.02,96.65 52.02,96.77 51.51,96.77 51.51,96.9 51.54,96.93 51.54,96.65
  Top 0.203: 52.12,97.41 51.99,97.41 v51.87,97.28 | 49.99,96.6 50.39,95.4 50.39,95.94 50.52,96.11 v50.11,96.27 | v50.11,96.27 50.32,96.8 | 52.68,97.08 52.76,97.05 C3.2 | v45.92,96.34 46.3,96.8 | D2.A 48.77,107.06
  Top 0.305: 50.32,96.8 51.44,96.8 | 46.3,96.8 48.9,96.8
  Top 0.406: C21.2 53.34,55.1 v51.97,55.17 | R19.1 50.22,54 v50.22,55.22 | C20.2 46.85,55.33 v45.9,55.32 | C30.2 53.42,34.65 v52.05,34.72 | R27.1 50.29,33.55 v50.29,34.77 | C29.2 46.93,34.88 v45.97,34.87 | C12.2 53.29,75.62 v51.92,75.69 | R11.1 50.16,74.52 v50.16,75.74 | C11.2 46.8,75.85 v45.85,75.84 | C3.2 53.24,96.14 v51.87,96.22 | R3.1 50.11,95.05 v50.11,96.27 | C2.2 46.75,96.38 v45.92,96.34
  Top 0.508: 50.7,53.57 50.62,53.65 50.57,53.72 | 50.7,53.57 50.67,53.57 R19.1 50.67,53.52 50.83,53.57 50.7,53.57 | R22.1 51.06,39.38 v50.09,39.37 | 50.77,33.12 50.7,33.2 50.65,33.27 | 50.77,33.12 50.75,33.12 R27.1 50.75,33.07 50.9,33.12 50.77,33.12 | R30.1 51.14,18.93 v50.16,18.92 | 50.65,74.09 50.57,74.17 50.52,74.24 | 50.65,74.09 50.62,74.09 R11.1 50.62,74.04 50.77,74.09 50.65,74.09 | R14.1 51.01,59.9 v50.04,59.89 | 50.6,94.61 50.52,94.69 50.47,94.77 | 50.6,94.61 50.57,94.61 R3.1 50.57,94.56 50.72,94.61 50.6,94.61 | R6.1 50.96,80.43 v49.99,80.42 | C20.2 47.44,55.23 47.45,55.22 47.47,55.24 v49.23,55.24
  Top 1.016: 48.77,107.06 X1.2
  Bottom 0.254: 38.66,20.24 38.68,20.24 | 41.53,61.01 41.55,61.01 | SJ100.2 38.1,20.24 | SJ1.2 45.9,108.41 45.97,108.33 47.04,108.33 47.04,109.83 45.87,109.83 | 44.96,109.83 45.87,109.83 | 45.87,109.83 45.87,110.44
  Bottom 0.406: v51.97,55.17 51.94,55.12 | v45.9,55.32 46.69,55.37 46.61,55.45 | v52.05,34.72 52.02,34.67 | v45.97,34.87 46.76,34.92 46.69,35 | v51.92,75.69 51.89,75.64 | v45.85,75.84 46.63,75.89 46.56,75.97 | v51.87,96.22 51.84,96.16 | v45.92,96.34 45.85,96.47
  other vias: 43.81,47.78 45.39,47.83 43.69,45.95 44.63,46.76 45.57,45.95 50.09,40.36 43.89,27.33 45.47,27.38 43.76,25.5 44.7,26.31 45.64,25.5 49.3,34.8 50.16,19.91 43.76,68.3 45.34,68.35 43.64,66.47 44.58,67.28 45.52,66.47 49.17,75.77 50.04,60.88 43.71,88.82 45.29,88.87 43.59,87 44.53,87.81 45.47,87 49.99,81.41
  pour Bottom: 38.71,109.86 60.27,109.86 60.25,17.25 38.68,17.25 38.68,36.83
HEAT
  Top 0.203: U7.14 20.04,57.33 20.04,55.7 20.6,55.22 22.23,55.22 22.45,54.99 22.45,52.3 23.14,51.66 23.14,46.35 22.96,46.18 22.96,45.14 23.14,44.96 23.14,41.22 22.66,40.74 22.66,39.52 22.91,39.27 25.17,39.27 26.09,38.33 26.09,30.91 26.29,30.71 28.02,30.71 28.19,30.53 R40.1 28.19,28.5 28.19,26.77 R43.1
HEAT2  (via drill 0.43)
  Top 0.203: v19.18,59.51 19.18,58.75 U7.13 | v23.95,52.88 v23.95,55.63 | v22.28,42.44 22.23,42.19 22.23,39.04 22.45,38.81 24.74,38.81 25.5,37.95 25.5,30.89 24.03,30.05 19.3,30.05 19.18,29.84 19.18,29.03 18.99,28.85 R41.1 18.99,28.54 18.29,27.84 18.29,26.54 19.07,25.76 R42.1
  Bottom 0.203: v19.18,59.51 19.41,59.51 19.91,59 23.55,59 23.88,58.65 23.88,55.93 23.95,55.85 v23.95,55.63 | v23.95,52.88 23.95,52.15 23.75,51.94 21.18,51.94 20.93,51.69 20.93,47.24 21.11,47.04 22.05,47.04 22.28,46.76 v22.28,42.44
LED1  (via drill 0.43)
  Top 0.203: v21.51,56.54 21.51,57.33 U7.16 | v9.8,56.95 9.8,55.73 R21.1
  Bottom 0.203: v9.8,56.95 9.8,57.28 10.52,57.68 11.66,57.68 12.45,57.02 16.51,57.02 17.86,56.67 19.68,56.67 19.81,56.54 v21.51,56.54
LIMIT_A  (via drill 0.43)
  Top 0.203: J18.1 32.72,113.08 R52.1 32.66,112.37 | v27.2,54.13 28.09,55.55 28.09,59.89 U7.23 | v19.91,53.26 19.68,53.57 19.46,53.8 18.03,53.8 17.86,54 17.86,55.83 17.65,56.03 17.65,59.03 18.01,59.49 v18.01,63.48 | v13.34,67.74 13.34,69.93 14.55,70.89 14.71,71.04 14.71,74.5 14.91,74.7 15.21,74.7 15.37,74.85 15.37,80.29 15.82,80.75 v15.82,87.96 | C59.1 33.03,108.52 33.88,109.37 33.88,112.17 33.68,112.37 32.66,112.37 | 32.64,112.39 32.66,112.37 | v31.32,112.39 32.64,112.39 | 32.64,112.39 32.72,112.45
  Bottom 0.203: v19.91,53.26 20.47,53.75 25.5,53.75 25.88,54.13 v27.2,54.13 | v18.01,63.48 18.01,64.52 17.78,64.75 16,64.75 15.77,64.97 15.77,67.77 15.42,68 14.1,68 13.84,67.74 v13.34,67.74 | v15.82,87.96 15.82,91.9 16.13,92.23 20.47,92.23 20.98,92.91 20.98,103 21.46,103.48 24.89,103.48 25.27,103.86 25.27,112.12 25.6,112.45 31.34,112.45 v31.32,112.39
LIMIT_X  (via drill 0.43)
  Top 0.203: v26.62,62.56 26.98,62.33 27.2,62.31 27.46,62.31 27.56,62.23 U7.26 | v12.83,70.69 12.8,70.79 12.32,71.27 12.32,73.15 12.14,73.38 12.14,77.37 11.96,77.55 v10.21,77.55 | v4.39,93.9 4.14,94.16 4.14,104.17 C56.1 4.14,105.59 4.14,107.9 4.29,108 R51.1 5.61,108.74 5.61,109.58 5.74,109.7 8.79,109.7 8.97,109.88 8.97,113.41 9.14,113.64 J15.4
  Bottom 0.203: v26.62,62.56 26.19,62.56 25.76,62.92 25.76,64.19 25.38,64.49 21.21,64.49 20.47,65.13 19.99,65.61 17.4,65.61 17.17,65.84 17.17,70.43 16.92,70.69 v12.83,70.69 | v10.21,77.55 1.6,77.55 1.35,77.8 1.35,83.26 1.68,83.59 3.17,83.59 3.33,83.69 3.33,92.28 3.45,92.46 4.22,92.46 4.39,92.69 v4.39,93.9
LIMIT_Y  (via drill 0.43)
  Top 0.203: v26.82,61.34 27,61.42 27.71,61.42 U7.25 | v20.45,64.03 19.13,65.35 v19.13,66.95 | v19.13,71.09 19.25,71.35 19.25,76.5 19.46,76.68 21.18,76.68 21.31,76.83 21.31,79.65 21.51,79.83 22.73,79.83 23.57,80.64 23.57,85.62 25.07,87.38 25.07,92.61 | 25.07,92.61 25.07,92.63 | 25.07,92.61 25.07,94.49 24.11,95.48 | 24.11,95.48 24.05,95.53 23.34,95.53 R49.1 | 24.11,95.48 24.16,95.53 24.16,100.97 23.93,101.22 C57.1 22.73,101.93 22.73,113.36 22.45,113.59 J16.4
  Bottom 0.203: v26.82,61.34 26.57,61.34 25.15,62.76 25.15,63.75 24.77,64.03 v20.45,64.03 | v19.13,66.95 v19.13,71.09
LIMIT_Z  (via drill 0.43)
  Top 0.203: v29.41,60.6 28.68,60.6 U7.24 | v32,60.71 32.03,61.34 31.62,61.8 31.62,63.42 30.96,64.24 30.96,78.89 30.73,79.12 30.73,86.79 30.38,87.35 30.38,88.47 30.91,89 30.91,90.6 | 30.91,90.6 30.91,90.65 | 30.91,90.6 30.91,90.78 31.24,91.11 31.24,92.2 30.07,93.45 30.07,98.96 29.82,99.14 R47.1 28.63,99.44 28.63,100.51 C58.1 29.03,101.93 29.03,113.41 28.88,113.64 J17.4
  Bottom 0.203: v29.41,60.6 v32,60.71
M1  (via drill 0.43)
  Top 0.203: U3.9 40.99,47.86 40.59,48.26 v40.59,48.72 | U4.9 41.06,27.42 40.82,27.66 40.82,27.84 v40.49,28.17 | U1.9 41.06,88.91 39.42,90.4 v37.03,91.19 | U2.9 41.34,68.39 40.56,69.47 36.98,69.47 36.58,69.93 36.58,71.45 36.8,71.7 36.8,73.91 v36.6,74.22 | v27.36,32.08 26.64,32.41 26.64,38.58 25.43,39.78 24.79,39.78 24.61,40.11 v24.61,40.62 | v7.82,53.62 8.74,53.62 8.74,53.65 8.91,53.82 8.91,57.38 8.64,57.66 v8.23,57.66 | v20.4,62.81 21.41,62.81 21.57,62.97 21.57,64.72 21.26,65.02 v21.26,65.61 | v29.69,88.98 29.69,87.38 30.25,86.54 30.25,79.81 29.34,78.72 29.34,76.4 v29.62,76.1 | v39.67,44.98 39.67,40.44 40.18,39.62 40.18,38.58 40.92,37.69 40.92,35.05 41.3,34.57 41.3,33.91 40.84,33.38 40.84,31.65 v40.46,31.42 | v35.38,68.94 35.38,69.52 34.95,69.95 34.95,72.11 34.47,72.59 34.47,73.84 v33.91,74.42 | v15.82,50.47 v14.05,50.47
  Bottom 0.203: v40.49,28.17 v40.46,31.42 40.36,31.14 33.76,31.14 33.17,31.77 33.1,31.88 32.92,32.05 S2.1 30.86,32.05 30.81,32.11 30.79,32.08 v27.36,32.08 | v37.03,91.19 37.11,91.16 35.74,91.16 35.64,91.06 31.42,91.06 30.48,90.04 v29.69,88.98 | v24.61,40.62 24.61,40.69 24.43,40.87 24.08,40.87 23.9,41.05 22.89,41.05 22.71,40.87 20.19,40.87 19.96,41.1 19.96,44.2 v19.36,44.37 19.28,44.3 18.54,45.03 16.66,45.03 16.38,45.31 16.38,47.75 15.82,48.31 v15.82,50.47 | v7.82,53.62 7.82,52.58 8.05,52.43 13.39,52.45 13.95,52.45 14.05,52.35 v14.05,50.47 | v8.23,57.66 8.91,58.55 9.63,59.33 13.03,59.33 13.44,58.88 14.53,58.88 14.81,59.18 17.25,59.18 17.37,59.36 17.37,61.19 17.58,61.39 20.19,61.39 20.4,61.59 v20.4,62.81 | v21.26,65.61 21.26,67 21.59,67.28 24.18,67.28 24.77,66.73 28.93,66.73 30.12,67.92 30.89,67.92 31.37,68.4 32.05,68.4 32.46,68 34.44,68 v35.38,68.94 | v29.62,76.1 30.5,75.06 33.07,75.08 33.73,74.42 33.81,74.42 33.83,74.4 33.86,74.42 v33.91,74.42 34.16,74.22 v36.6,74.22 | v40.59,48.72 39.73,48.72 39.52,48.51 39.52,45.52 v39.67,44.98
M2  (via drill 0.43)
  Top 0.203: U3.10 40.47,47.36 38.99,49.1 37.62,49.1 37.16,49.51 v36.63,49.51 | U4.10 40.55,26.92 39.78,27.66 37.44,27.66 37.26,27.81 37.26,28.96 v37.29,29.06 | U1.10 40.37,88.41 39.29,89.41 37.03,89.41 v36.35,89.97 | U2.10 41.05,67.89 40.18,68.99 36.65,68.99 35.76,69.9 v35.76,71.91 35.76,72.26 35.03,73 35.03,76.89 34.85,77.01 34.04,77.01 33.15,77.9 32.79,77.9 32.18,78.59 32.18,81.1 31.65,81.64 31.65,87 32.13,87.61 32.13,89.31 v31.75,90.19 | v35.23,34.65 35.23,32.44 35.76,31.9 v35.76,29.03 | v29.34,47.78 29.74,47.37 29.74,38.38 29.18,37.8 29.18,36.5 30.3,35.13 S2.2 | v21.79,48.18 21.46,48.59 21.46,54.23 21.26,54.46 19.79,54.89 v19.07,55.75 | v11.25,56.87 11.23,57.07 11,57.28 11,59.33 10.79,59.87 10.79,66.7 10.44,67.06 9.07,67.06 8.81,67.41 8.81,69.67 9.02,69.85 10.54,69.85 10.72,70.03 v10.72,71.91
  Bottom 0.203: v35.23,34.65 32.33,34.65 S2.2 | v36.35,89.97 35.84,90.19 v31.75,90.19 | v21.79,48.18 28.68,48.18 28.88,47.98 v29.34,47.78 30.43,48.51 31.52,48.51 32.51,49.51 36.55,49.51 | v19.07,55.75 17.75,56.08 16.43,56.49 12.14,56.49 11.48,56.74 v11.25,56.87 | v10.72,71.91 22.86,71.93 23.11,72.14 24.71,72.14 25.07,72.42 25.93,72.42 26.44,71.91 v35.76,71.91 | v35.76,29.03 35.94,29.01 35.99,29.06 v37.29,29.06 | 36.55,49.51 36.58,49.53 v36.63,49.51 36.55,49.51
M3  (via drill 0.43)
  Top 0.203: U3.11 40.28,46.86 38.99,48.26 35.66,48.26 35.48,48.46 v35.48,52.58 | U4.11 40.36,26.42 39.67,27.18 35.99,27.18 v35.99,27.28 | U1.11 40.18,87.91 38.96,88.88 35.66,88.88 v35.36,89.05 35.13,89.48 35.13,93.9 v34.77,94.26 | U2.11 40.23,67.39 v39.57,68.05 | v10.29,81 11.96,81 12.12,81.15 v12.12,82.83 | v6.53,81.51 6.58,81.38 6.58,69.34 6.33,68.96 6.33,68.2 6.68,67.84 6.68,60.45 6.07,59.49 v6.07,57.28 | 28.52,52.88 28.52,49.73 27.94,49.3 27.94,47.14 28.73,46.3 28.73,38.99 28.37,38.63 v28.12,38.63 | 28.6,52.88 28.63,52.91 v28.5,52.63 28.5,52.88 28.52,52.88 | 28.52,52.88 v28.52,54.48 | v39.67,65.56 39.67,61.24 v39.7,61.09 | v41.15,56.16 41.15,54.3 40.79,53.95 40.79,52.15 40.62,51.94 39.09,51.94 v38.73,51.84 | v31.22,27.86 31.22,26.39 v30.61,26.01
  Bottom 0.203: v35.99,27.28 35.33,27.18 31.6,27.18 31.19,27.48 31.19,28.07 v31.22,27.86 | v34.77,94.26 34.57,94.28 29.97,94.31 28.78,93.24 22.53,93.24 21.59,92.25 21.59,91.54 21.39,91.34 17.6,91.34 17.4,91.14 17.4,83.13 17.09,82.83 v12.12,82.83 | v10.29,81 6.81,81 v6.53,81.51 | v6.07,57.28 6.07,56.97 5.71,56.62 5.71,55.47 5.89,55.22 8.15,55.22 9.45,54.25 16.1,54.25 16.46,54.43 19.18,54.43 19.61,54.94 22.48,54.94 22.81,54.33 25.2,54.33 25.78,55.02 28.07,55.02 v28.52,54.48 | v28.5,52.63 28.93,52.6 v35.48,52.58 35.43,52.58 36.17,51.84 v38.73,51.84 | v39.57,68.05 39.57,65.89 v39.67,65.56 | v39.7,61.09 39.7,57.61 v41.15,56.16 | v28.12,38.63 28.12,37.13 26.09,37.13 25.93,36.96 25.93,26.16 26.11,25.98 30.18,25.98 30.2,26.01 v30.61,26.01
  Bottom 0.254: 28.12,37.13 S2.3
MISO  (via drill 0.43)
  Top 0.203: R13.1 4.65,64.06 4.65,66.22 J3.1 | 15.01,67.13 15.01,69.55 15.24,69.77 16.64,69.77 16.74,69.95 16.74,75.13 16.89,75.41 16.89,86.79 17.09,87 17.42,87 17.65,87.22 17.65,98.22 16.89,98.22 J7.7 | 15.01,67.13 15.06,67.08 15.77,67.08 U7.2 | v14.96,67.03 14.96,67.08 15.01,67.13
  Bottom 0.203: v14.96,67.03 14.91,66.98 9.12,66.98 8.76,67.33 7.54,67.33 7.19,66.98 J3.1
MOSI  (via drill 0.43)
  Top 0.203: v13.84,87.66 13.84,93.67 13.99,93.8 15.72,93.8 J7.3 | v9.3,82.63 7.82,82.63 7.52,82.32 7.52,81.1 7.09,80.42 7.09,68.61 | 7.09,68.61 7.09,59.97 R18.1 | v16.08,68.81 16.08,68.05 U7.1 | 7.09,68.61 v7.14,68.61
  Bottom 0.203: v9.3,82.63 10.31,82.63 10.72,83.06 10.72,87.35 11.02,87.66 v13.84,87.66 | v16.08,68.81 15.77,68.61 v7.14,68.61 6.68,68.4 4.39,68.4 3.07,69.52 J3.4 2.18,69.52
N$1
  Top 0.203: U3.13 41.87,45.86 41.86,45.87 41.83,45.85 39.5,45.85 | 39.5,45.85 38.81,45.85 R20.1 38.63,45.82 38.68,45.87 39.5,45.85
N$1_A
  Top 0.203: R28.1 38.89,25.4 41.91,25.4 41.94,25.43 41.95,25.42 U4.13
N$1_B
  Top 0.203: U2.13 41.82,66.39 41.81,66.4 41.78,66.37 38.76,66.37 R12.1 38.58,66.34 38.63,66.4
N$1_B_C
  Top 0.203: R4.1 38.71,86.89 41.73,86.89 41.76,86.92 41.77,86.91 U1.13
N$2
  Top 0.203: U3.24 47.78,46.41 48.31,46.59 49.56,46.59 49.12,46.2 49.07,46.25 49,46.25 49,46.35 49.1,46.46 48.92,46.46 48.87,46.41 48.87,46.3 48.72,46.46 48.72,46.53 48.49,46.53 47.78,46.33 48.34,46.26 48.79,46.18 48.39,46.38 48.4,46.39 48.52,46.39 48.73,46.19 49.35,45.97 49.15,46.36 49.53,46.28
  Top 0.813: 49.53,46.28 54.17,46.29 54.18,46.25 56.03,43.97 J21.3 57.3,43.94
N$2_A
  Top 0.203: U4.24 47.85,25.96 48.39,26.14 49.64,26.14 49.2,25.76 49.15,25.81 49.07,25.81 49.07,25.91 49.17,26.01 49,26.01 48.95,25.96 48.95,25.86 48.79,26.01 48.79,26.09 48.56,26.09 47.85,25.88 48.42,25.81 48.87,25.73 48.46,25.93 48.47,25.94 48.6,25.94 48.81,25.74 49.43,25.53 49.23,25.92 49.61,25.83
  Top 0.813: 49.61,25.83 54.25,25.84 54.25,25.81 56.11,23.52 J20.3 57.38,23.5
N$2_B
  Top 0.203: U2.24 47.73,66.93 48.26,67.11 49.51,67.11 49.07,66.73 49.02,66.78 48.95,66.78 48.95,66.88 49.05,66.98 48.87,66.98 48.82,66.93 48.82,66.83 48.67,66.98 48.67,67.06 48.44,67.06 47.73,66.85 48.29,66.78 48.74,66.7 48.34,66.9 48.34,66.91 48.47,66.91 48.68,66.71 49.3,66.5 49.1,66.89 49.48,66.8
  Top 0.813: 49.48,66.8 54.12,66.81 54.13,66.78 55.98,64.49 J23.3 57.25,64.47
N$2_B_C
  Top 0.203: U1.24 47.68,87.45 48.21,87.64 49.46,87.64 49.02,87.25 48.97,87.3 48.9,87.3 48.9,87.4 49,87.5 48.82,87.5 48.77,87.45 48.77,87.35 48.62,87.5 48.62,87.58 48.39,87.58 47.68,87.38 48.24,87.31 48.69,87.22 48.28,87.43 48.29,87.44 48.42,87.44 48.63,87.23 49.25,87.02 49.05,87.41 49.43,87.33
  Top 0.813: 49.43,87.33 54.07,87.31 54.08,87.3 55.93,85.01 J22.3 57.2,84.99
N$3
  Top 0.203: U3.21 46.27,44.8 46.81,44.07 46.41,44.36 46.41,44.35
  Top 0.508: 46.41,44.35 47.4,43.08 46.58,43.76 46.38,43.94 46.91,42.8 47.04,42.77 47.19,42.62
  Top 0.813: 47.19,42.62 49.45,42.62 51,41.94 54.1,41.94 55.17,41.43 J21.4
N$3_A
  Top 0.203: U4.21 46.34,24.35 46.89,23.62 46.48,23.92 46.48,23.9
  Top 0.508: 46.48,23.9 47.47,22.63 46.66,23.32 46.46,23.5 46.99,22.35 47.12,22.33 47.27,22.12
  Top 0.813: 47.27,22.12 49.53,22.12 51.08,21.49 54.18,21.49 55.24,20.98 J20.4
N$3_B
  Top 0.203: U2.21 46.22,65.32 46.76,64.59 46.35,64.89 46.35,64.87
  Top 0.508: 46.35,64.87 47.32,63.55 46.53,64.29 46.33,64.47 47.12,63.35 47.35,63.37 47.27,63.37
  Top 0.813: 47.24,63.37 47.27,63.37 48.18,62.46 54.05,62.46 55.12,61.95 J23.4
N$3_B_C
  Top 0.203: U1.21 46.17,85.84 46.71,85.11 46.3,85.41 46.3,85.39
  Top 0.508: 46.3,85.39 47.3,84.12 46.48,84.81 46.28,84.99 46.84,83.67 46.97,83.64 47.12,83.64
  Top 0.813: 47.12,83.64 49.38,83.64 50.9,82.98 54,82.98 55.07,82.47 J22.4
N$4
  Top 0.203: U3.26 47.83,47.42 48.39,47.47 49.33,47.7 47.75,47.32 48.41,47.17 49.33,47.09 48.31,47.35 49.12,47.37
  Top 0.61: 49.12,47.37 49.51,47.39
  Top 0.813: 49.51,47.39 49.45,47.39 49.45,47.4 55.78,47.4 56.34,46.48 57.71,46.48 J21.2
N$4_A
  Top 0.203: U4.26 47.9,26.98 48.46,27.03 49.4,27.25 47.83,26.87 48.49,26.72 49.4,26.64 48.39,26.9 49.2,26.92
  Top 0.61: 49.2,26.92 49.58,26.94
  Top 0.813: 49.58,26.94 49.52,26.94 49.53,26.95 55.85,26.95 56.41,26.04 57.78,26.04 J20.2
N$4_B
  Top 0.203: U2.26 47.78,67.94 48.34,68 49.28,68.22 47.7,67.84 48.36,67.69 49.28,67.61 48.26,67.87 49.07,67.89
  Top 0.61: 49.07,67.89 49.45,67.91
  Top 0.813: 49.45,67.91 49.4,67.91 49.4,67.92 55.73,67.92 56.29,67 57.66,67 J23.2
N$4_B_C
  Top 0.203: U1.26 47.73,88.47 48.28,88.52 49.23,88.75 47.65,88.37 48.31,88.21 49.23,88.14 48.21,88.39 49.02,88.42
  Top 0.61: 49.02,88.42 49.4,88.44
  Top 0.813: 49.4,88.44 49.34,88.44 49.35,88.44 55.68,88.44 56.24,87.53 57.61,87.53 J22.2
N$5
  Top 0.203: U3.1 46.46,49.53 46.74,49.69 46.91,49.84 47.21,50.12 47.46,50.43 47.64,50.69 47.38,50.69 47.38,50.48 46.76,49.86 46.3,49.61 46.3,49.68 47.22,50.6 47.12,50.72 47.22,50.83 47.22,50.85 46.23,49.84 46.51,50.16 46.53,50.22 46.65,50.43 47.02,50.93 47.14,51.05 47.5,51
  Top 0.406: 57.84,49.07 57.86,49.07 57.86,49.05 J21.1
  Top 0.813: 47.5,51 55.07,51 57.84,49.07 57.86,49.1
N$5_A
  Top 0.203: U4.1 46.53,29.08 46.81,29.25 46.99,29.39 47.28,29.68 47.53,29.98 47.71,30.24 47.46,30.24 47.46,30.03 46.84,29.41 46.38,29.16 46.38,29.23 47.3,30.15 47.19,30.28 47.3,30.38 47.3,30.4 46.3,29.39 46.58,29.72 46.61,29.77 46.72,29.98 47.09,30.48 47.22,30.61 47.57,30.56
  Top 0.406: 57.91,28.63 57.94,28.63 57.94,28.6 J20.1
  Top 0.813: 47.57,30.56 55.14,30.56 57.91,28.63 57.94,28.65
N$5_B
  Top 0.203: U2.1 46.41,70.05 46.69,70.22 46.86,70.36 47.16,70.65 47.41,70.95 47.59,71.21 47.33,71.21 47.33,71 46.71,70.38 46.25,70.13 46.25,70.21 47.17,71.12 47.07,71.25 47.17,71.35 47.17,71.37 46.18,70.36 46.46,70.69 46.48,70.74 46.59,70.95 46.97,71.45 47.09,71.58 47.45,71.53
  Top 0.406: 57.78,69.6 57.81,69.6 57.81,69.57 J23.1
  Top 0.813: 47.45,71.53 55.02,71.53 57.78,69.6 57.81,69.62
N$5_B_C
  Top 0.203: U1.1 46.35,90.58 46.63,90.74 46.81,90.88 47.11,91.17 47.36,91.48 47.53,91.73 47.28,91.73 47.28,91.53 46.66,90.91 46.2,90.65 46.2,90.73 47.12,91.64 47.02,91.77 47.12,91.87 47.12,91.9 46.13,90.88 46.41,91.21 46.43,91.26 46.54,91.48 46.91,91.97 47.04,92.1 47.4,92.05
  Top 0.406: 57.73,90.12 57.76,90.12 57.76,90.09 J22.1
  Top 0.813: 47.4,92.05 54.97,92.05 57.73,90.12 57.76,90.14
N$6
  Top 0.203: U3.8 41.88,48.36 41.68,48.44 41.68,49.51 41.5,49.68 40.39,49.68 40.21,49.89 40.21,50.6 C23.1
N$6_A
  Top 0.203: U4.8 41.96,27.92 41.76,27.99 41.76,29.06 41.58,29.23 39.65,29.23 39.47,29.44 C32.1
N$6_B
  Top 0.203: U2.8 41.83,68.89 41.68,68.94 41.68,70 41.45,70.21 40.34,70.21 40.16,70.41 40.16,71.12 C14.1
N$6_B_C
  Top 0.203: U1.8 41.78,89.41 41.76,89.43 41.76,90.5 41.53,90.73 40.28,90.73 40.11,90.93 40.11,91.64 C5.1
N$8
  Top 0.203: 49.71,39.42 49.71,40.49 50.62,40.49 | 50.62,40.49 50.7,40.49 | 50.62,40.49 50.55,40.41 50.55,39.62 50.52,39.6 50.52,39.83 | 50.52,39.83 50.52,39.88 | 50.52,39.83 50.49,39.8 49.68,39.8 49.68,39.93 49.71,39.95 50.44,39.95
N$8_A
  Top 0.203: 49.78,18.97 49.78,20.04 50.7,20.04 | 50.7,20.04 50.77,20.04 | 50.7,20.04 50.62,19.96 50.62,19.18 50.6,19.15 50.6,19.38 | 50.6,19.38 50.6,19.43 | 50.6,19.38 50.57,19.36 49.76,19.36 49.76,19.48 49.78,19.51 50.52,19.51
N$8_B
  Top 0.203: 49.66,59.94 49.66,61.01 50.57,61.01 | 50.57,61.01 50.65,61.01 | 50.57,61.01 50.49,60.94 50.49,60.15 50.47,60.12 50.47,60.35 | 50.47,60.35 50.47,60.4 | 50.47,60.35 50.44,60.33 49.63,60.33 49.63,60.45 49.66,60.48 50.39,60.48
N$8_B_C
  Top 0.203: 49.61,80.47 49.61,81.53 50.52,81.53 | 50.52,81.53 50.6,81.53 | 50.52,81.53 50.44,81.46 50.44,80.67 50.42,80.64 50.42,80.87 | 50.42,80.87 50.42,80.92 | 50.42,80.87 50.39,80.85 49.58,80.85 49.58,80.97 49.61,81 50.34,81
N$9
  Top 0.203: R34.1 11.2,42.44 9.12,42.44 J5.2
N$10
  Top 0.203: U3.23 47.76,45.91 48.54,45.85 48.26,45.64 48.08,45.82 47.8,45.82 48.41,45.26 48.59,45.82 48.62,45.49
  Top 0.254: R22.2 52.61,44.64 52.58,44.68 50.52,44.68
  Top 0.813: 48.62,45.49 50.01,44.88 50.52,44.68
N$10_A
  Top 0.203: U4.23 47.84,25.47 48.62,25.4 48.34,25.2 48.16,25.38 47.88,25.38 48.49,24.82 48.67,25.38 48.69,25.04
  Top 0.254: R30.2 52.69,24.2 52.65,24.23 50.6,24.23
  Top 0.813: 48.69,25.04 50.09,24.43 50.6,24.23
N$10_B
  Top 0.203: U2.23 47.71,66.44 48.49,66.37 48.21,66.17 48.03,66.34 47.75,66.34 48.36,65.79 48.54,66.34 48.56,66.02
  Top 0.254: R14.2 52.56,65.17 52.53,65.2 50.47,65.2
  Top 0.813: 48.56,66.02 49.96,65.41 50.47,65.2
N$10_B_C
  Top 0.203: U1.23 47.66,86.96 48.44,86.89 48.16,86.69 47.98,86.87 47.7,86.87 48.31,86.31 48.49,86.87 48.51,86.54
  Top 0.254: R6.2 52.51,85.69 52.48,85.72 50.42,85.72
  Top 0.813: 48.51,86.54 49.91,85.93 50.42,85.72
N$11
  Top 0.203: U3.27 47.89,47.97 48.21,48.31 48.67,48.67 48.72,48.46 48.31,48.13 47.8,47.83 48.34,47.9 48.9,48.11 48.9,48.26 48.23,47.9 48.87,48.41
  Top 0.254: R19.2 51.27,49.08 50.55,48.74
  Top 0.813: 48.87,48.41 50.55,48.74
N$11_A
  Top 0.203: U4.27 47.97,27.52 48.28,27.86 48.74,28.22 48.79,28.02 48.39,27.69 47.88,27.38 48.41,27.46 48.97,27.66 48.97,27.81 48.31,27.46 48.95,27.96
  Top 0.254: R27.2 51.34,28.64 50.62,28.3
  Top 0.813: 48.95,27.96 50.62,28.3
N$11_B
  Top 0.203: U2.27 47.84,68.49 48.16,68.83 48.62,69.19 48.67,68.99 48.26,68.66 47.75,68.35 48.28,68.43 48.84,68.63 48.84,68.78 48.18,68.43 48.82,68.94
  Top 0.254: R11.2 51.22,69.61 50.49,69.27
  Top 0.813: 48.82,68.94 50.49,69.27
N$11_B_C
  Top 0.203: U1.27 47.79,89.01 48.11,89.36 48.56,89.71 48.62,89.51 48.21,89.18 47.7,88.88 48.23,88.95 48.79,89.15 48.79,89.31 48.13,88.95 48.77,89.46
  Top 0.254: R3.2 51.16,90.13 50.44,89.79
  Top 0.813: 48.77,89.46 50.44,89.79
N$12
  Top 0.203: R33.1 9.12,41.48 J5.3
N$13
  Top 0.203: J5.1 9.12,43.1 | 9.98,44.09 L1.1
  Top 0.305: 9.12,43.1 9.78,43.1 10.01,43.38 9.98,44.07 9.98,44.09
N$14
  Top 0.203: R23.2 4.28,16.58 4.47,16.38 8.84,16.38 9.02,16.2 9.02,14.73 9.14,14.61 10.31,14.61 10.34,14.63 10.36,14.61 U12.4
N$15
  Top 0.203: U7.7 15.77,63.02 13.41,63.02 13.21,63.14 13.21,65.25 13.08,65.41 12.37,65.41 Q1.3 11.66,66.12 11.66,66.88 10.49,67.84 10.08,67.84 C42.1
N$16  (via drill 0.43)
  Top 0.203: v8.05,94.92 15.72,94.92 J7.4 | v19.58,93.65 19.43,93.6 20.14,93.6 C37.1 | v8.05,87.66 8.05,84.86 L2.1
  Bottom 0.203: 8.05,94.08 8.33,94.08 8.76,94.06 15.57,94.06 15.98,93.65 v19.58,93.65 | v8.05,87.66 8.05,94.08 | 8.05,94.08 v8.05,94.92
N$17
  Top 0.203: R21.2 7.49,55.14 4.75,55.14 LD4.P$2
N$18
  Top 0.203: U6.11 16.54,51.38 14.07,51.38 13.89,51.56 13.89,52.05 R35.1
N$19
  Top 0.203: U3.5 44.18,50.61 43.87,51 42.34,51 42.16,51.13 42.11,51.26 42.13,52.13 C22.1
N$19_A
  Top 0.203: U4.5 44.26,30.17 43.94,30.56 42.39,30.56 42.22,30.68 42.2,31.69 C31.1
N$19_B
  Top 0.203: U2.5 44.13,71.14 43.81,71.53 42.29,71.53 42.11,71.65 42.06,71.78 42.08,72.66 C13.1
N$19_B_C
  Top 0.203: U1.5 44.08,91.66 43.76,92.05 42.24,92.05 42.06,92.18 42.06,93.27 42.02,93.25 C4.1
N$20
  Top 0.203: U3.4 44.68,51.94 44.66,52.31 C22.2
N$20_A
  Top 0.203: U4.4 44.76,31.5 44.74,31.86 C31.2
N$20_B
  Top 0.203: U2.4 44.63,72.47 44.61,72.83 C13.2
N$20_B_C
  Top 0.203: U1.4 44.58,92.99 44.56,93.36 C4.2
N$21
  Top 0.203: U3.6 43.68,50.33 43.56,50.44 41.4,50.44 41.22,50.67 41.22,53.7 41.73,54.15 C19.2
N$21_A
  Top 0.203: U4.6 43.76,29.88 43.64,30 41.53,30 41.35,30.23 41.35,33.12 41.78,33.71 C28.2
N$21_B
  Top 0.203: U2.6 43.63,70.85 43.51,70.97 41.35,70.97 41.17,71.2 41.17,74.17 41.63,74.68 C10.2
N$21_B_C
  Top 0.203: U1.6 43.58,91.37 43.46,91.49 41.3,91.49 41.12,91.72 41.12,95.07 41.27,95.2 C1.2
N$22
  Top 0.203: R37.2 33.66,104.78 33.66,105.49 R36.1 34.72,105.13 34.92,104.93 34.92,104.47 35.38,103.96 35.38,102.97 35.46,102.95 U10.5
N$23
  Top 0.203: R24.2 41.48,38.76 41.48,37.36 41.83,37.11 45.39,37.11 45.59,37.31 45.59,39.75 45.75,39.94 46.95,39.94 46.97,39.96 R55.3
N$23_A
  Top 0.203: R32.2 41.68,18.29 41.68,17.14 41.86,16.97 45.47,16.97 45.67,17.17 45.67,19.56 45.83,19.74 R54.3
N$23_B
  Top 0.203: R16.2 41.55,59.26 41.55,58.24 41.66,58.14 45.34,58.14 45.54,58.34 45.54,60.63 45.7,60.81 46.86,60.81 46.87,60.81 R15.3
N$23_B_C
  Top 0.203: R8.2 41.25,79.81 41.25,78.74 41.45,78.51 45.36,78.51 45.57,78.72 45.57,81.25 45.78,81.44 46.86,81.44 46.86,81.46 R7.3
N$24
  Top 0.203: U3.17 44.18,44.15 44.17,44.15 44.17,42.9 43.76,42.49 43.76,41.35 43.76,41.09 43.76,39.12 44.14,38.74 R55.2
N$24_A
  Top 0.203: U4.17 44.26,23.71 44.25,23.7 44.25,22.45 43.84,22 43.84,20.85 43.83,20.59 43.83,18.9 44.22,18.52 R54.2
N$24_B
  Top 0.203: U2.17 44.13,64.68 44.12,64.67 44.12,63.42 43.71,63.02 43.71,61.87 43.71,61.56 43.71,60.45 43.71,59.98 44.07,59.64 R15.2
N$24_B_C
  Top 0.203: U1.17 44.08,85.2 44.07,85.19 44.07,83.95 43.66,83.54 43.66,82.4 43.66,82.14 43.66,80.68 R7.2
N$25
  Top 0.203: R26.1 6.22,51.89 4.85,51.89 LD1.P$1
N$26  (via drill 0.43)
  Top 0.203: U10.4 35.46,96.77 33.86,95.43 C70.1 33.35,94 33.35,93.24 v32.69,92.43 | v24.08,90.5 23.34,90.5 R56.2
  Bottom 0.203: v24.08,90.5 27.96,90.53 28.91,91.62 29.87,92.73 30.73,92.73 31.04,92.43 v32.69,92.43
N$27
  Top 0.203: R56.1 20.55,89.33 20.55,87.91 C71.1
N$29  (via drill 0.43)
  Top 0.203: v36.73,100.1 36.83,100.1 | U10.1 31.55,98.37 | v41.4,102.64 41.44,102.68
